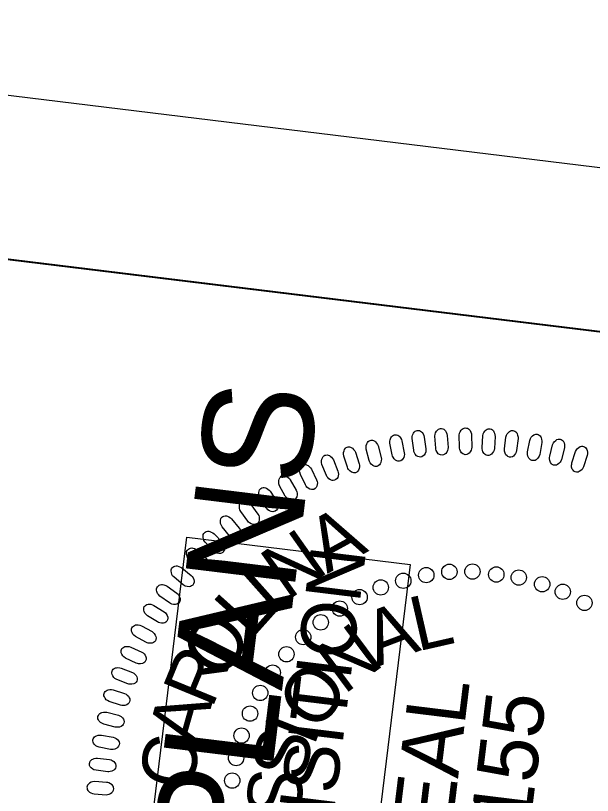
# Model space of a CAD drawing. Extents: x 480792 to 482083, y 490046 to 491850.
# Drawn here: x 481064.9 to 481125.1, y 491768.8 to 491850.2 of the extents above; entities that cross this region are included whole.
import ezdxf

# ---------------------------------------------------------------- set-up
doc = ezdxf.new("R2010")
doc.units = 0
for name, color, linetype in [('Sheet PE Seal Cell', 7, 'Continuous'), ('Sheet Plan CELL', 7, 'Continuous'), ('Sheet Plot Border Outside CELL', 7, 'Continuous'), ('Sheet Sticker Incomplete CELL', 7, 'Continuous')]:
    doc.layers.add(name, color=color, linetype=linetype)

msp = doc.modelspace()

# ---------------------------------------------------------------- linework, layer by layer
at = {"layer": 'Sheet PE Seal Cell'}
for points in [[(481104.194, 491804.324), (481103.96, 491805.529), (481103.955, 491805.752), (481103.979, 491805.899), (481104.057, 491806.086), (481104.131, 491806.213), (481104.226, 491806.313), (481104.321, 491806.372), (481104.427, 491806.412), (481104.541, 491806.414), (481104.664, 491806.408), (481104.778, 491806.369), (481104.9, 491806.291), (481104.974, 491806.225), (481105.069, 491806.09), (481105.162, 491805.926), (481105.215, 491805.773), (481105.462, 491804.541), (481105.472, 491804.371), (481105.454, 491804.225), (481105.397, 491804.052), (481105.314, 491803.893), (481105.234, 491803.796), (481105.091, 491803.707), (481104.948, 491803.659), (481104.794, 491803.67), (481104.682, 491803.699), (481104.538, 491803.772), (481104.388, 491803.915), (481104.287, 491804.079), (481104.233, 491804.2)], [(481106.441, 491804.801), (481106.284, 491806.017), (481106.292, 491806.239), (481106.325, 491806.385), (481106.415, 491806.568), (481106.497, 491806.689), (481106.598, 491806.782), (481106.697, 491806.835), (481106.805, 491806.869), (481106.919, 491806.865), (481107.042, 491806.85), (481107.152, 491806.805), (481107.269, 491806.719), (481107.339, 491806.648), (481107.425, 491806.508), (481107.508, 491806.337), (481107.551, 491806.182), (481107.72, 491804.937), (481107.72, 491804.766), (481107.693, 491804.622), (481107.625, 491804.452), (481107.532, 491804.299), (481107.446, 491804.207), (481107.298, 491804.128), (481107.152, 491804.089), (481106.999, 491804.109), (481106.889, 491804.145), (481106.75, 491804.227), (481106.61, 491804.38), (481106.52, 491804.549), (481106.473, 491804.674)], [(481108.741, 491805.033), (481108.659, 491806.257), (481108.682, 491806.479), (481108.724, 491806.622), (481108.825, 491806.798), (481108.915, 491806.914), (481109.022, 491807.002), (481109.123, 491807.048), (481109.234, 491807.076), (481109.347, 491807.063), (481109.469, 491807.04), (481109.577, 491806.988), (481109.688, 491806.896), (481109.753, 491806.82), (481109.83, 491806.675), (481109.901, 491806.5), (481109.935, 491806.343), (481110.026, 491805.089), (481110.014, 491804.918), (481109.979, 491804.776), (481109.9, 491804.611), (481109.798, 491804.464), (481109.706, 491804.378), (481109.553, 491804.308), (481109.405, 491804.278), (481109.254, 491804.308), (481109.146, 491804.351), (481109.012, 491804.442), (481108.882, 491804.603), (481108.802, 491804.778), (481108.765, 491804.905)], [(481111.21, 491805.133), (481111.206, 491806.359), (481111.242, 491806.579), (481111.294, 491806.719), (481111.405, 491806.889), (481111.502, 491806.999), (481111.614, 491807.079), (481111.718, 491807.12), (481111.83, 491807.14), (481111.943, 491807.12), (481112.063, 491807.091), (481112.168, 491807.032), (481112.272, 491806.932), (481112.332, 491806.853), (481112.4, 491806.703), (481112.461, 491806.524), (481112.484, 491806.364), (481112.496, 491805.108), (481112.474, 491804.938), (481112.43, 491804.798), (481112.341, 491804.639), (481112.229, 491804.498), (481112.132, 491804.418), (481111.976, 491804.357), (481111.826, 491804.337), (481111.677, 491804.377), (481111.572, 491804.426), (481111.444, 491804.525), (481111.324, 491804.694), (481111.256, 491804.874), (481111.226, 491805.004)], [(481113.587, 491805.088), (481113.66, 491806.312), (481113.71, 491806.529), (481113.77, 491806.665), (481113.892, 491806.828), (481113.996, 491806.932), (481114.113, 491807.005), (481114.219, 491807.038), (481114.332, 491807.052), (481114.443, 491807.025), (481114.561, 491806.988), (481114.662, 491806.923), (481114.76, 491806.817), (481114.815, 491806.733), (481114.874, 491806.58), (481114.923, 491806.397), (481114.936, 491806.237), (481114.869, 491804.982), (481114.837, 491804.814), (481114.783, 491804.677), (481114.685, 491804.523), (481114.564, 491804.391), (481114.463, 491804.317), (481114.303, 491804.266), (481114.152, 491804.255), (481114.005, 491804.304), (481113.903, 491804.36), (481113.783, 491804.467), (481113.674, 491804.643), (481113.616, 491804.826), (481113.595, 491804.957)], [(481115.918, 491804.953), (481116.068, 491806.171), (481116.132, 491806.384), (481116.2, 491806.516), (481116.332, 491806.671), (481116.442, 491806.769), (481116.563, 491806.834), (481116.671, 491806.86), (481116.786, 491806.866), (481116.894, 491806.833), (481117.01, 491806.789), (481117.106, 491806.717), (481117.198, 491806.605), (481117.247, 491806.519), (481117.296, 491806.362), (481117.334, 491806.177), (481117.336, 491806.016), (481117.191, 491804.767), (481117.148, 491804.602), (481117.086, 491804.469), (481116.978, 491804.321), (481116.85, 491804.196), (481116.744, 491804.129), (481116.581, 491804.088), (481116.43, 491804.087), (481116.286, 491804.145), (481116.189, 491804.207), (481116.074, 491804.321), (481115.977, 491804.504), (481115.932, 491804.691), (481115.917, 491804.823)], [(481118.337, 491804.625), (481118.562, 491805.831), (481118.639, 491806.039), (481118.716, 491806.167), (481118.858, 491806.313), (481118.974, 491806.403), (481119.098, 491806.461), (481119.208, 491806.481), (481119.323, 491806.48), (481119.429, 491806.439), (481119.541, 491806.388), (481119.633, 491806.31), (481119.717, 491806.193), (481119.761, 491806.104), (481119.8, 491805.944), (481119.826, 491805.756), (481119.819, 491805.595), (481119.595, 491804.359), (481119.542, 491804.197), (481119.472, 491804.068), (481119.355, 491803.927), (481119.219, 491803.811), (481119.109, 491803.75), (481118.943, 491803.72), (481118.792, 491803.728), (481118.653, 491803.795), (481118.56, 491803.863), (481118.453, 491803.984), (481118.367, 491804.172), (481118.333, 491804.362), (481118.328, 491804.494)], [(481101.791, 491803.738), (481101.481, 491804.925), (481101.463, 491805.146), (481101.477, 491805.295), (481101.543, 491805.487), (481101.61, 491805.618), (481101.698, 491805.723), (481101.789, 491805.788), (481101.893, 491805.836), (481102.006, 491805.844), (481102.13, 491805.846), (481102.246, 491805.815), (481102.372, 491805.744), (481102.45, 491805.683), (481102.553, 491805.555), (481102.657, 491805.396), (481102.718, 491805.247), (481103.043, 491804.033), (481103.064, 491803.864), (481103.056, 491803.717), (481103.009, 491803.54), (481102.936, 491803.377), (481102.862, 491803.275), (481102.725, 491803.177), (481102.585, 491803.12), (481102.431, 491803.121), (481102.317, 491803.143), (481102.168, 491803.207), (481102.01, 491803.342), (481101.9, 491803.498), (481101.838, 491803.616)], [(481120.639, 491804.175), (481120.94, 491805.365), (481121.03, 491805.568), (481121.115, 491805.691), (481121.265, 491805.829), (481121.386, 491805.911), (481121.514, 491805.96), (481121.625, 491805.974), (481121.74, 491805.965), (481121.843, 491805.919), (481121.952, 491805.86), (481122.038, 491805.777), (481122.115, 491805.654), (481122.154, 491805.563), (481122.183, 491805.401), (481122.196, 491805.212), (481122.179, 491805.052), (481121.878, 491803.832), (481121.815, 491803.672), (481121.737, 491803.548), (481121.611, 491803.416), (481121.469, 491803.308), (481121.355, 491803.254), (481121.188, 491803.235), (481121.038, 491803.252), (481120.903, 491803.328), (481120.814, 491803.401), (481120.715, 491803.529), (481120.641, 491803.723), (481120.619, 491803.914), (481120.622, 491804.046)], [(481099.527, 491803.027), (481099.143, 491804.193), (481099.111, 491804.413), (481099.116, 491804.562), (481099.17, 491804.758), (481099.228, 491804.892), (481099.31, 491805.004), (481099.396, 491805.074), (481099.497, 491805.128), (481099.61, 491805.144), (481099.733, 491805.153), (481099.851, 491805.129), (481099.981, 491805.067), (481100.063, 491805.01), (481100.174, 491804.888), (481100.286, 491804.737), (481100.358, 491804.592), (481100.758, 491803.401), (481100.789, 491803.233), (481100.79, 491803.086), (481100.755, 491802.907), (481100.692, 491802.739), (481100.625, 491802.633), (481100.494, 491802.527), (481100.358, 491802.461), (481100.204, 491802.452), (481100.089, 491802.467), (481099.937, 491802.522), (481099.771, 491802.646), (481099.65, 491802.795), (481099.582, 491802.909)], [(481122.961, 491803.492), (481123.336, 491804.66), (481123.438, 491804.857), (481123.53, 491804.975), (481123.689, 491805.102), (481123.815, 491805.177), (481123.946, 491805.219), (481124.058, 491805.224), (481124.171, 491805.209), (481124.271, 491805.156), (481124.376, 491805.091), (481124.458, 491805.002), (481124.527, 491804.875), (481124.56, 491804.781), (481124.578, 491804.618), (481124.58, 491804.429), (481124.553, 491804.27), (481124.176, 491803.071), (481124.103, 491802.917), (481124.017, 491802.797), (481123.883, 491802.673), (481123.734, 491802.574), (481123.617, 491802.528), (481123.449, 491802.519), (481123.301, 491802.546), (481123.171, 491802.629), (481123.086, 491802.709), (481122.995, 491802.842), (481122.934, 491803.04), (481122.924, 491803.232), (481122.936, 491803.364)], [(481097.325, 491802.181), (481096.869, 491803.32), (481096.823, 491803.537), (481096.819, 491803.686), (481096.859, 491803.885), (481096.909, 491804.023), (481096.984, 491804.139), (481097.067, 491804.215), (481097.163, 491804.275), (481097.275, 491804.298), (481097.397, 491804.315), (481097.516, 491804.299), (481097.65, 491804.245), (481097.735, 491804.193), (481097.854, 491804.079), (481097.975, 491803.934), (481098.056, 491803.795), (481098.53, 491802.631), (481098.572, 491802.465), (481098.582, 491802.318), (481098.558, 491802.137), (481098.506, 491801.967), (481098.446, 491801.856), (481098.322, 491801.742), (481098.191, 491801.668), (481098.037, 491801.649), (481097.921, 491801.656), (481097.766, 491801.702), (481097.592, 491801.815), (481097.463, 491801.957), (481097.387, 491802.066)], [(481095.138, 491801.178), (481094.611, 491802.285), (481094.551, 491802.5), (481094.537, 491802.648), (481094.566, 491802.85), (481094.607, 491802.991), (481094.674, 491803.111), (481094.751, 491803.192), (481094.844, 491803.258), (481094.954, 491803.288), (481095.075, 491803.312), (481095.195, 491803.303), (481095.333, 491803.258), (481095.421, 491803.212), (481095.546, 491803.105), (481095.677, 491802.969), (481095.765, 491802.835), (481096.312, 491801.703), (481096.364, 491801.54), (481096.383, 491801.395), (481096.371, 491801.212), (481096.329, 491801.037), (481096.276, 491800.924), (481096.16, 491800.802), (481096.033, 491800.72), (481095.881, 491800.692), (481095.766, 491800.692), (481095.607, 491800.728), (481095.427, 491800.829), (481095.289, 491800.963), (481095.206, 491801.067)], [(481093.036, 491800.023), (481092.441, 491801.096), (481092.367, 491801.306), (481092.345, 491801.453), (481092.361, 491801.657), (481092.393, 491801.799), (481092.452, 491801.923), (481092.524, 491802.009), (481092.613, 491802.081), (481092.721, 491802.118), (481092.839, 491802.15), (481092.96, 491802.148), (481093.1, 491802.112), (481093.191, 491802.071), (481093.323, 491801.972), (481093.462, 491801.845), (481093.559, 491801.716), (481094.175, 491800.621), (481094.237, 491800.462), (481094.266, 491800.317), (481094.265, 491800.135), (481094.234, 491799.958), (481094.188, 491799.841), (481094.08, 491799.713), (481093.959, 491799.623), (481093.809, 491799.585), (481093.694, 491799.578), (481093.534, 491799.604), (481093.347, 491799.694), (481093.201, 491799.818), (481093.112, 491799.918)], [(481091.05, 491798.795), (481090.389, 491799.828), (481090.302, 491800.033), (481090.271, 491800.179), (481090.274, 491800.382), (481090.297, 491800.527), (481090.348, 491800.655), (481090.415, 491800.745), (481090.498, 491800.822), (481090.604, 491800.866), (481090.721, 491800.905), (481090.841, 491800.911), (481090.983, 491800.883), (481091.076, 491800.848), (481091.214, 491800.758), (481091.36, 491800.639), (481091.465, 491800.517), (481092.149, 491799.463), (481092.221, 491799.308), (481092.259, 491799.166), (481092.269, 491798.983), (481092.25, 491798.805), (481092.212, 491798.685), (481092.112, 491798.55), (481091.996, 491798.453), (481091.849, 491798.406), (481091.734, 491798.392), (481091.573, 491798.407), (481091.381, 491798.486), (481091.227, 491798.601), (481091.132, 491798.694)], [(481089.121, 491797.406), (481088.396, 491798.396), (481088.297, 491798.595), (481088.256, 491798.739), (481088.247, 491798.942), (481088.26, 491799.087), (481088.303, 491799.218), (481088.364, 491799.313), (481088.443, 491799.395), (481088.546, 491799.445), (481088.66, 491799.492), (481088.779, 491799.505), (481088.923, 491799.487), (481089.018, 491799.457), (481089.161, 491799.376), (481089.315, 491799.267), (481089.428, 491799.152), (481090.176, 491798.142), (481090.258, 491797.992), (481090.304, 491797.853), (481090.326, 491797.671), (481090.318, 491797.492), (481090.287, 491797.37), (481090.196, 491797.229), (481090.087, 491797.125), (481089.943, 491797.068), (481089.829, 491797.047), (481089.667, 491797.052), (481089.471, 491797.119), (481089.31, 491797.224), (481089.21, 491797.311)], [(481087.229, 491795.88), (481086.443, 491796.823), (481086.331, 491797.015), (481086.282, 491797.156), (481086.26, 491797.358), (481086.264, 491797.504), (481086.299, 491797.637), (481086.354, 491797.735), (481086.427, 491797.822), (481086.526, 491797.879), (481086.637, 491797.932), (481086.756, 491797.953), (481086.9, 491797.944), (481086.998, 491797.921), (481087.145, 491797.849), (481087.305, 491797.749), (481087.425, 491797.641), (481088.235, 491796.681), (481088.326, 491796.536), (481088.381, 491796.4), (481088.414, 491796.22), (481088.418, 491796.042), (481088.394, 491795.917), (481088.312, 491795.771), (481088.21, 491795.66), (481088.07, 491795.595), (481087.958, 491795.566), (481087.796, 491795.562), (481087.596, 491795.615), (481087.429, 491795.71), (481087.323, 491795.791)], [(481085.511, 491794.305), (481084.668, 491795.196), (481084.544, 491795.381), (481084.486, 491795.518), (481084.451, 491795.719), (481084.446, 491795.865), (481084.473, 491796), (481084.521, 491796.101), (481084.59, 491796.193), (481084.684, 491796.255), (481084.792, 491796.316), (481084.909, 491796.344), (481085.054, 491796.344), (481085.152, 491796.327), (481085.303, 491796.264), (481085.47, 491796.175), (481085.596, 491796.075), (481086.465, 491795.167), (481086.566, 491795.029), (481086.629, 491794.896), (481086.673, 491794.719), (481086.688, 491794.54), (481086.673, 491794.415), (481086.6, 491794.264), (481086.504, 491794.147), (481086.369, 491794.073), (481086.258, 491794.037), (481086.098, 491794.023), (481085.895, 491794.064), (481085.722, 491794.148), (481085.611, 491794.222)], [(481083.876, 491792.596), (481082.978, 491793.433), (481082.843, 491793.61), (481082.776, 491793.743), (481082.729, 491793.941), (481082.715, 491794.086), (481082.733, 491794.223), (481082.775, 491794.327), (481082.837, 491794.423), (481082.928, 491794.491), (481083.031, 491794.558), (481083.146, 491794.594), (481083.291, 491794.602), (481083.39, 491794.592), (481083.546, 491794.539), (481083.717, 491794.46), (481083.85, 491794.368), (481084.774, 491793.517), (481084.882, 491793.384), (481084.954, 491793.256), (481085.01, 491793.082), (481085.036, 491792.905), (481085.027, 491792.779), (481084.964, 491792.624), (481084.877, 491792.501), (481084.746, 491792.418), (481084.638, 491792.376), (481084.479, 491792.351), (481084.273, 491792.379), (481084.096, 491792.453), (481083.98, 491792.519)], [(481082.369, 491790.766), (481081.421, 491791.544), (481081.275, 491791.712), (481081.201, 491791.841), (481081.141, 491792.035), (481081.117, 491792.18), (481081.127, 491792.317), (481081.163, 491792.423), (481081.219, 491792.523), (481081.305, 491792.597), (481081.404, 491792.67), (481081.516, 491792.713), (481081.66, 491792.731), (481081.76, 491792.726), (481081.918, 491792.684), (481082.095, 491792.616), (481082.232, 491792.532), (481083.208, 491791.74), (481083.325, 491791.615), (481083.404, 491791.492), (481083.471, 491791.322), (481083.508, 491791.147), (481083.508, 491791.021), (481083.455, 491790.861), (481083.375, 491790.733), (481083.25, 491790.643), (481083.144, 491790.594), (481082.986, 491790.558), (481082.78, 491790.574), (481082.598, 491790.636), (481082.479, 491790.695)], [(481080.943, 491788.867), (481079.948, 491789.583), (481079.793, 491789.742), (481079.71, 491789.866), (481079.638, 491790.056), (481079.606, 491790.199), (481079.607, 491790.337), (481079.635, 491790.445), (481079.684, 491790.548), (481079.767, 491790.627), (481079.861, 491790.706), (481079.97, 491790.757), (481080.112, 491790.783), (481080.212, 491790.785), (481080.373, 491790.753), (481080.553, 491790.695), (481080.696, 491790.621), (481081.72, 491789.892), (481081.844, 491789.775), (481081.931, 491789.657), (481082.008, 491789.491), (481082.056, 491789.318), (481082.064, 491789.192), (481082.021, 491789.03), (481081.949, 491788.897), (481081.83, 491788.799), (481081.728, 491788.743), (481081.572, 491788.699), (481081.365, 491788.701), (481081.18, 491788.751), (481081.057, 491788.803)], [(481079.678, 491786.881), (481078.64, 491787.535), (481078.474, 491787.683), (481078.384, 491787.802), (481078.3, 491787.987), (481078.259, 491788.127), (481078.252, 491788.265), (481078.273, 491788.375), (481078.316, 491788.48), (481078.393, 491788.564), (481078.482, 491788.65), (481078.588, 491788.707), (481078.729, 491788.742), (481078.828, 491788.75), (481078.991, 491788.727), (481079.174, 491788.682), (481079.321, 491788.617), (481080.389, 491787.953), (481080.52, 491787.844), (481080.614, 491787.732), (481080.702, 491787.571), (481080.76, 491787.401), (481080.776, 491787.277), (481080.743, 491787.112), (481080.68, 491786.975), (481080.567, 491786.87), (481080.469, 491786.808), (481080.317, 491786.753), (481080.11, 491786.742), (481079.922, 491786.781), (481079.797, 491786.825)], [(481078.479, 491784.77), (481077.402, 491785.356), (481077.228, 491785.495), (481077.13, 491785.607), (481077.035, 491785.787), (481076.985, 491785.925), (481076.968, 491786.061), (481076.983, 491786.172), (481077.019, 491786.28), (481077.09, 491786.369), (481077.174, 491786.46), (481077.277, 491786.523), (481077.415, 491786.567), (481077.513, 491786.582), (481077.676, 491786.569), (481077.863, 491786.536), (481078.014, 491786.479), (481079.121, 491785.885), (481079.259, 491785.783), (481079.36, 491785.677), (481079.457, 491785.522), (481079.527, 491785.357), (481079.55, 491785.234), (481079.527, 491785.067), (481079.473, 491784.926), (481079.367, 491784.814), (481079.273, 491784.746), (481079.124, 491784.682), (481078.918, 491784.659), (481078.728, 491784.685), (481078.6, 491784.721)], [(481077.473, 491782.592), (481076.361, 491783.11), (481076.178, 491783.237), (481076.074, 491783.343), (481075.967, 491783.517), (481075.909, 491783.651), (481075.884, 491783.786), (481075.892, 491783.898), (481075.921, 491784.008), (481075.987, 491784.101), (481076.065, 491784.197), (481076.163, 491784.267), (481076.297, 491784.319), (481076.395, 491784.34), (481076.559, 491784.338), (481076.747, 491784.316), (481076.901, 491784.269), (481078.043, 491783.745), (481078.188, 491783.654), (481078.295, 491783.553), (481078.402, 491783.405), (481078.481, 491783.244), (481078.512, 491783.123), (481078.5, 491782.955), (481078.455, 491782.811), (481078.356, 491782.692), (481078.266, 491782.619), (481078.123, 491782.545), (481077.919, 491782.509), (481077.727, 491782.523), (481077.597, 491782.551)], [(481076.583, 491780.434), (481075.441, 491780.881), (481075.25, 491780.996), (481075.139, 491781.096), (481075.022, 491781.262), (481074.955, 491781.392), (481074.922, 491781.526), (481074.923, 491781.638), (481074.945, 491781.75), (481075.004, 491781.847), (481075.076, 491781.948), (481075.17, 491782.023), (481075.301, 491782.084), (481075.397, 491782.111), (481075.561, 491782.119), (481075.75, 491782.109), (481075.907, 491782.072), (481077.08, 491781.621), (481077.229, 491781.537), (481077.342, 491781.445), (481077.458, 491781.303), (481077.548, 491781.148), (481077.587, 491781.029), (481077.585, 491780.861), (481077.549, 491780.714), (481077.457, 491780.59), (481077.373, 491780.51), (481077.234, 491780.428), (481077.032, 491780.378), (481076.841, 491780.382), (481076.709, 491780.401)], [(481075.833, 491778.203), (481074.665, 491778.578), (481074.468, 491778.681), (481074.351, 491778.773), (481074.224, 491778.932), (481074.149, 491779.058), (481074.107, 491779.189), (481074.101, 491779.301), (481074.116, 491779.414), (481074.169, 491779.514), (481074.234, 491779.619), (481074.324, 491779.7), (481074.45, 491779.77), (481074.544, 491779.802), (481074.707, 491779.82), (481074.897, 491779.823), (481075.056, 491779.795), (481076.255, 491779.419), (481076.409, 491779.345), (481076.528, 491779.26), (481076.653, 491779.126), (481076.751, 491778.976), (481076.798, 491778.86), (481076.807, 491778.692), (481076.78, 491778.544), (481076.697, 491778.413), (481076.617, 491778.329), (481076.483, 491778.239), (481076.285, 491778.176), (481076.094, 491778.167), (481075.961, 491778.178)], [(481075.265, 491775.916), (481074.076, 491776.217), (481073.872, 491776.307), (481073.75, 491776.392), (481073.613, 491776.542), (481073.53, 491776.663), (481073.481, 491776.791), (481073.467, 491776.902), (481073.475, 491777.016), (481073.523, 491777.12), (481073.581, 491777.228), (481073.664, 491777.315), (481073.787, 491777.392), (481073.879, 491777.431), (481074.04, 491777.46), (481074.229, 491777.473), (481074.389, 491777.456), (481075.609, 491777.155), (481075.768, 491777.092), (481075.892, 491777.015), (481076.025, 491776.888), (481076.133, 491776.745), (481076.187, 491776.632), (481076.206, 491776.465), (481076.189, 491776.315), (481076.114, 491776.18), (481076.04, 491776.09), (481075.912, 491775.991), (481075.718, 491775.917), (481075.527, 491775.896), (481075.394, 491775.899)], [(481074.805, 491773.592), (481073.599, 491773.818), (481073.39, 491773.894), (481073.263, 491773.972), (481073.116, 491774.113), (481073.026, 491774.229), (481072.968, 491774.354), (481072.949, 491774.464), (481072.95, 491774.578), (481072.99, 491774.684), (481073.041, 491774.796), (481073.119, 491774.888), (481073.236, 491774.973), (481073.326, 491775.017), (481073.485, 491775.056), (481073.673, 491775.081), (481073.833, 491775.075), (481075.07, 491774.85), (481075.233, 491774.798), (481075.362, 491774.728), (481075.502, 491774.61), (481075.619, 491774.475), (481075.68, 491774.364), (481075.71, 491774.199), (481075.702, 491774.048), (481075.635, 491773.909), (481075.566, 491773.815), (481075.445, 491773.708), (481075.257, 491773.622), (481075.068, 491773.589), (481074.935, 491773.583)], [(481074.493, 491771.254), (481073.275, 491771.403), (481073.062, 491771.467), (481072.929, 491771.536), (481072.775, 491771.668), (481072.678, 491771.778), (481072.612, 491771.898), (481072.585, 491772.007), (481072.579, 491772.121), (481072.613, 491772.23), (481072.657, 491772.345), (481072.729, 491772.441), (481072.84, 491772.533), (481072.927, 491772.583), (481073.084, 491772.631), (481073.269, 491772.669), (481073.431, 491772.672), (481074.678, 491772.526), (481074.844, 491772.484), (481074.977, 491772.422), (481075.124, 491772.314), (481075.25, 491772.185), (481075.317, 491772.079), (481075.357, 491771.916), (481075.359, 491771.765), (481075.301, 491771.622), (481075.239, 491771.524), (481075.125, 491771.41), (481074.942, 491771.312), (481074.755, 491771.267), (481074.623, 491771.253)], [(481074.366, 491770.146), (481073.142, 491770.218), (481072.92, 491770.193), (481072.778, 491770.15), (481072.602, 491770.048), (481072.487, 491769.957), (481072.401, 491769.85), (481072.355, 491769.748), (481072.328, 491769.637), (481072.342, 491769.524), (481072.364, 491769.403), (481072.417, 491769.295), (481072.511, 491769.184), (481072.587, 491769.12), (481072.733, 491769.044), (481072.908, 491768.974), (481073.066, 491768.942), (481074.32, 491768.861), (481074.491, 491768.873), (481074.633, 491768.91), (481074.797, 491768.989), (481074.943, 491769.093), (481075.029, 491769.185), (481075.098, 491769.339), (481075.127, 491769.487), (481075.095, 491769.639), (481075.052, 491769.746), (481074.96, 491769.878), (481074.798, 491770.008), (481074.622, 491770.085), (481074.495, 491770.123)]]:
    msp.add_lwpolyline(points, close=True, dxfattribs=at)
for centre in [(481107.756, 491791.77), (481110.167, 491792.116), (481112.578, 491792.142), (481115.069, 491791.837), (481105.356, 491791.181), (481117.412, 491791.521), (481103.006, 491790.489), (481119.855, 491790.82), (481100.795, 491789.476), (481122.006, 491790.035), (481124.272, 491788.875), (481098.723, 491788.286), (481096.74, 491786.844), (481094.906, 491785.304), (481093.161, 491783.512), (481091.723, 491781.602), (481090.419, 491779.476), (481089.353, 491777.32), (481088.469, 491775.022), (481087.902, 491772.684), (481087.493, 491770.328)]:
    msp.add_circle(centre, 0.801, dxfattribs=at)
at = {"layer": 'Sheet Plan CELL'}
for points in [[(481016.186, 491830.584), (480834.326, 490341.611), (481876.581, 490214.312), (482058.438, 491703.26)], [(481041.344, 491726.742), (481053.454, 491825.994), (481165.138, 491812.366), (481153.027, 491713.102)]]:
    msp.add_lwpolyline(points, close=True, dxfattribs=at)
at = {"layer": 'Sheet Plot Border Outside CELL'}
msp.add_lwpolyline([(481878.743, 490046.324), (482082.845, 491717.405), (480995.922, 491850.16), (480791.82, 490179.078)], close=True, dxfattribs=at)
at = {"layer": 'Sheet Sticker Incomplete CELL'}
msp.add_lwpolyline([(481088.269, 491646.965), (481064.942, 491649.814), (481082.764, 491795.73), (481106.09, 491792.881)], close=True, dxfattribs=at)

# ---------------------------------------------------------------- texts
at = {"layer": 'Sheet PE Seal Cell'}
for s, height, rotation, p in [('A', 5.669, 28.70934, (481097.41, 491791.89)), ('N', 5.669, 35.19869, (481093.255, 491789.053)), ('I', 5.669, 41.68805, (481091.627, 491787.433)), ('L', 5.669, 48.17741, (481089.461, 491784.985)), ('L', 5.669, 12.86737, (481106.832, 491783.796)), ('A', 5.669, 20.80717, (481102.609, 491782.173)), ('O', 5.669, 54.66676, (481086.375, 491780.594)), ('N', 5.669, 36.68676, (481099.147, 491779.234)), ('R', 5.669, 67.64548, (481085.367, 491777.74)), ('O', 5.669, 52.56636, (481096.337, 491775.233)), ('SEAL', 6.2363, 83.01787, (481109.713, 491759.446)), ('46155', 6.2363, 83.01787, (481117.448, 491756.136)), ('A', 5.669, 74.13483, (481084.069, 491773.661)), ('I', 5.669, 68.44595, (481095.984, 491773.761)), ('S', 5.669, 76.38575, (481094.896, 491770.065)), ('C', 5.669, 80.62419, (481083.307, 491769.144)), ('S', 5.669, 84.32554, (481094.529, 491766.221))]:
    msp.add_text(s, height=height, rotation=rotation, dxfattribs=at).set_placement(p)
at = {"layer": 'Sheet Sticker Incomplete CELL'}
for s, height, p in [('INCOMPLETE PLANS', 11.52, (481077.74, 491657.268)), ('DO NOT USE FOR R/W ACQUISITION', 5.76, (481085.033, 491659.651))]:
    msp.add_text(s, height=height, rotation=83.03651, dxfattribs=at).set_placement(p)

doc.saveas('drawing.dxf')
